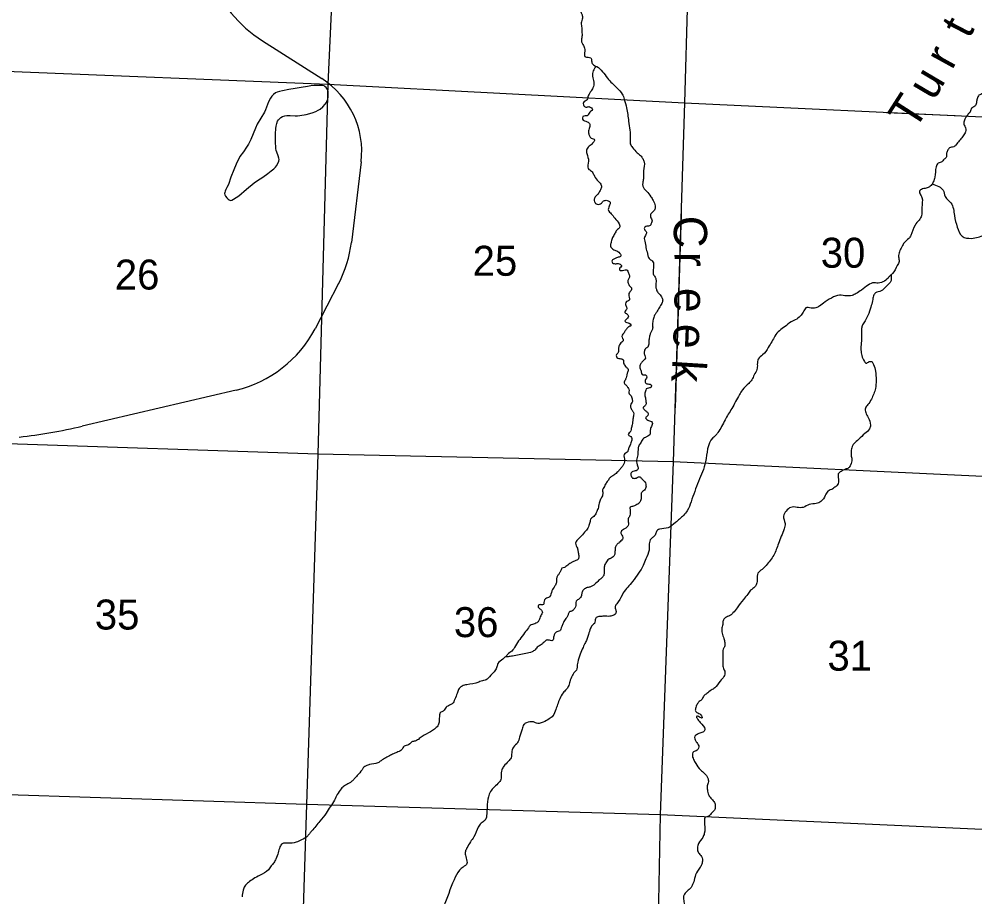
# Model space of a CAD drawing. Extents: x 1219626 to 1426462, y 456797 to 752399.
# Drawn here: x 1266561 to 1280912, y 533009 to 546194 of the extents above; entities that cross this region are included whole.
import ezdxf

# ---------------------------------------------------------------- set-up
doc = ezdxf.new("R2010")
doc.units = 0
for name, color, linetype in [('Lakes and Ponds', 7, 'Continuous'), ('Masks', 7, 'Continuous'), ('Narrow River Creek and Branch and Slough', 7, 'Continuous'), ('Narrow River Creek and Branch and Slough Text', 7, 'Continuous'), ('Section Lines', 7, 'Continuous'), ('Section Numbers', 7, 'Continuous'), ('Uninventoried Roads and Features', 7, 'Continuous')]:
    doc.layers.add(name, color=color, linetype=linetype)

msp = doc.modelspace()

# ---------------------------------------------------------------- linework, layer by layer
at = {"layer": 'Lakes and Ponds'}
msp.add_lwpolyline([(1269876, 544129), (1269818, 544016), (1269783, 543929), (1269742, 543820), (1269703, 543711), (1269682, 543667), (1269664, 543634), (1269653, 543609), (1269648, 543590), (1269646, 543576), (1269649, 543555), (1269658, 543534), (1269679, 543507), (1269698, 543489), (1269713, 543478), (1269724, 543473), (1269741, 543469), (1269757, 543473), (1269782, 543487), (1269821, 543513), (1269858, 543542), (1269975, 543639), (1270090, 543734), (1270140, 543771), (1270218, 543821), (1270296, 543873), (1270347, 543913), (1270384, 543945), (1270409, 543971), (1270426, 543991), (1270446, 544024), (1270461, 544060), (1270464, 544083), (1270462, 544103), (1270451, 544139), (1270429, 544194), (1270420, 544222), (1270415, 544250), (1270411, 544361), (1270411, 544472), (1270415, 544549), (1270421, 544588), (1270429, 544627), (1270442, 544660), (1270456, 544683), (1270469, 544698), (1270491, 544718), (1270518, 544732), (1270550, 544740), (1270579, 544744), (1270629, 544745), (1270704, 544742), (1270741, 544742), (1270778, 544745), (1270869, 544763), (1270960, 544787), (1271015, 544807), (1271053, 544826), (1271080, 544843), (1271120, 544874), (1271157, 544914), (1271172, 544936), (1271183, 544956), (1271196, 544993), (1271201, 545021), (1271203, 545062), (1271200, 545102), (1271192, 545136), (1271183, 545152), (1271170, 545168), (1271153, 545182), (1271139, 545190), (1271117, 545197), (1271095, 545199), (1270992, 545196), (1270940, 545191), (1270889, 545184), (1270797, 545168), (1270705, 545152), (1270609, 545135), (1270514, 545118), (1270470, 545108), (1270437, 545096), (1270413, 545085), (1270381, 545063), (1270354, 545035), (1270334, 545006), (1270308, 544954), (1270278, 544873), (1270262, 544833), (1270243, 544795), (1270188, 544705), (1270136, 544615), (1270109, 544558), (1270075, 544471), (1270039, 544385), (1270004, 544318), (1269975, 544269), (1269928, 544198), (1269876, 544129)], dxfattribs=at)
at = {"layer": 'Masks'}
for p, q in [((1279585, 544793), (1280614, 544744)), ((1276500, 543269), (1276409, 540356))]:
    msp.add_line(p, q, dxfattribs=at)
at = {"layer": 'Narrow River Creek and Branch and Slough'}
for points in [[(1273909, 549297), (1273931, 549227), (1273957, 549175), (1274000, 549110), (1274044, 549058), (1274087, 549019), (1274148, 548967), (1274191, 548928), (1274200, 548897), (1274213, 548867), (1274243, 548850), (1274308, 548841), (1274343, 548858), (1274399, 548867), (1274417, 548841), (1274460, 548785), (1274486, 548746), (1274504, 548693), (1274504, 548641), (1274512, 548602), (1274508, 548576), (1274495, 548546), (1274530, 548511), (1274569, 548476), (1274612, 548437), (1274612, 548359), (1274603, 548294), (1274586, 548251), (1274560, 548199), (1274525, 548155), (1274525, 548112), (1274556, 548077), (1274595, 548034), (1274647, 547964), (1274664, 547890), (1274694, 547804), (1274712, 547751), (1274729, 547717), (1274760, 547678), (1274799, 547647), (1274872, 547643), (1274920, 547656), (1274976, 547647), (1275024, 547617), (1275037, 547582), (1275050, 547539), (1275083, 547465), (1275127, 547399), (1275131, 547356), (1275114, 547291), (1275088, 547200), (1275079, 547156), (1275048, 547126), (1275022, 547091), (1274992, 547026), (1274979, 546935), (1274975, 546818), (1274979, 546735), (1274975, 546692), (1274949, 546653), (1274923, 546601), (1274918, 546544), (1274931, 546483), (1274966, 546397), (1274966, 546349), (1274996, 546301), (1275014, 546258), (1275018, 546210), (1275001, 546136), (1275009, 546062), (1275009, 546010), (1275014, 545967), (1275005, 545897), (1275005, 545854), (1275027, 545811), (1275048, 545759), (1275057, 545715), (1275048, 545667), (1275057, 545633), (1275105, 545620), (1275144, 545611), (1275157, 545568), (1275161, 545537), (1275200, 545498), (1275235, 545481), (1275396, 545307), (1275539, 545159), (1275617, 545068), (1275647, 544990), (1275682, 544859), (1275712, 544660)], [(1281992, 546706), (1281965, 546641), (1281938, 546593), (1281911, 546561), (1281874, 546539), (1281810, 546523), (1281777, 546486), (1281772, 546437), (1281820, 546395), (1281815, 546368), (1281777, 546341), (1281745, 546325), (1281713, 546293), (1281686, 546250), (1281681, 546212), (1281697, 546132), (1281702, 546084), (1281681, 546041), (1281659, 546019), (1281627, 546025), (1281595, 546003), (1281579, 545901), (1281542, 545853), (1281472, 545783), (1281424, 545767), (1281386, 545751), (1281381, 545660), (1281354, 545569), (1281316, 545520), (1281274, 545494), (1281257, 545461), (1281231, 545402), (1281209, 545365), (1281188, 545333), (1281123, 545295), (1281081, 545252), (1281059, 545220), (1281032, 545150), (1281027, 545102), (1281016, 545070), (1280984, 545059), (1280952, 545011), (1280936, 544957), (1280931, 544920), (1280898, 544877), (1280861, 544855), (1280839, 544802), (1280813, 544770), (1280780, 544721), (1280754, 544678), (1280748, 544614), (1280770, 544560), (1280764, 544485), (1280727, 544426), (1280625, 544303), (1280593, 544276), (1280529, 544260), (1280502, 544217), (1280486, 544168), (1280486, 544126), (1280448, 544088), (1280416, 544050), (1280362, 544029), (1280330, 543975), (1280309, 543820), (1280287, 543750), (1280255, 543697), (1280196, 543659), (1280127, 543643), (1280078, 543605), (1280089, 543568), (1280116, 543514), (1280116, 543364), (1280110, 543241), (1280073, 543176), (1280014, 543101), (1279950, 542946), (1279918, 542897), (1279853, 542839), (1279816, 542774), (1279778, 542699), (1279767, 542624), (1279773, 542554), (1279746, 542495), (1279674, 542371), (1279636, 542337), (1279608, 542304), (1279438, 542229), (1279400, 542233), (1279310, 542200), (1279211, 542124)], [(1275222, 545489), (1275182, 545415), (1275169, 545337), (1275189, 545247), (1275176, 545163), (1275143, 545105), (1275118, 545066), (1275098, 545014), (1275085, 544982), (1275034, 544943), (1275034, 544904), (1275072, 544872), (1275118, 544879), (1275169, 544833), (1275130, 544795), (1275092, 544743), (1275027, 544730), (1275021, 544691), (1275092, 544652), (1275130, 544614), (1275118, 544549), (1275111, 544484), (1275124, 544439), (1275150, 544407), (1275201, 544381), (1275182, 544342), (1275137, 544297), (1275085, 544239), (1275085, 544174), (1275111, 544058), (1275105, 543948), (1275156, 543909), (1275189, 543858), (1275240, 543774), (1275285, 543728), (1275305, 543670), (1275285, 543619), (1275253, 543567), (1275221, 543535), (1275195, 543489), (1275201, 543451), (1275240, 543412), (1275305, 543431), (1275337, 543464), (1275389, 543470), (1275434, 543444), (1275421, 543386), (1275408, 543321), (1275453, 543270), (1275505, 543205), (1275570, 543121), (1275576, 543063), (1275537, 543024), (1275505, 542972), (1275473, 542914), (1275453, 542850), (1275440, 542798), (1275466, 542746), (1275518, 542720), (1275582, 542675), (1275595, 542636), (1275557, 542617), (1275511, 542598), (1275473, 542578), (1275460, 542559), (1275473, 542533), (1275524, 542520), (1275570, 542520), (1275608, 542481), (1275582, 542456), (1275576, 542430), (1275641, 542423), (1275679, 542430), (1275712, 542378), (1275725, 542333), (1275718, 542300), (1275699, 542255), (1275705, 542229), (1275731, 542184), (1275757, 542145), (1275750, 542120), (1275718, 542074), (1275718, 542036), (1275718, 541965), (1275679, 541952), (1275666, 541919), (1275679, 541868), (1275686, 541842), (1275654, 541797), (1275666, 541777), (1275684, 541770)], [(1280272, 543718), (1280370, 543678), (1280434, 543625), (1280466, 543529), (1280508, 543476), (1280551, 543433), (1280604, 543242), (1280647, 543071), (1280721, 542933), (1280859, 542901), (1281051, 542954), (1281274, 543093), (1281402, 543167), (1281541, 543220), (1281700, 543220), (1281828, 543220), (1281934, 543306), (1282073, 543327), (1282211, 543327), (1282349, 543263), (1282456, 543284), (1282637, 543306), (1282860, 543316), (1283063, 543370), (1283222, 543370), (1283403, 543359), (1283541, 543348), (1283744, 543391), (1284020, 543487), (1284212, 543529), (1284404, 543561), (1284553, 543615), (1284702, 543668), (1284904, 543710), (1285127, 543785), (1285393, 543849), (1285606, 543870), (1285766, 543902), (1285926, 543902), (1286053, 543966), (1286234, 544009), (1286458, 544051), (1286713, 544051), (1286820, 544072), (1286915, 544009), (1286979, 543987), (1287064, 544062), (1287181, 544136), (1287309, 544200), (1287543, 544222), (1287809, 544243), (1287937, 544243), (1288033, 544307), (1288118, 544371), (1288256, 544445), (1288310, 544498), (1288437, 544573), (1288533, 544647), (1288629, 544733), (1288714, 544829), (1288767, 544914), (1288821, 545020), (1288852, 545073), (1288916, 545180)], [(1275712, 544660), (1275730, 544525), (1275738, 544416), (1275738, 544321), (1275769, 544265), (1275842, 544186), (1275890, 544143), (1275925, 544100), (1275947, 544048), (1275938, 543917), (1275934, 543796), (1275925, 543735), (1275925, 543687), (1275981, 543609), (1276046, 543527), (1276081, 543470), (1276111, 543388), (1276107, 543340), (1276072, 543292), (1276046, 543269), (1276042, 543222), (1276064, 543165), (1276055, 543135), (1276038, 543096), (1276012, 543083), (1275986, 543083), (1275955, 543070), (1275955, 543026), (1275981, 542996), (1275973, 542961), (1275947, 542900), (1275955, 542857), (1275973, 542761), (1275994, 542675), (1276007, 542627), (1276042, 542579), (1276068, 542562), (1276085, 542531), (1276085, 542453), (1276081, 542410), (1276081, 542366), (1276111, 542319), (1276124, 542271), (1276120, 542180), (1276129, 542136), (1276151, 542088), (1276185, 542054), (1276207, 542023), (1276224, 541976), (1276211, 541924), (1276172, 541858), (1276129, 541789), (1276103, 541746), (1276081, 541680), (1276072, 541611), (1276072, 541550), (1276055, 541507), (1276038, 541468), (1276025, 541420), (1276016, 541355), (1276012, 541298), (1275999, 541268), (1275968, 541246), (1275947, 541194), (1275955, 541142), (1275964, 541103), (1275942, 541073), (1275912, 541042), (1275886, 540999), (1275886, 540942), (1275903, 540895), (1275916, 540856), (1275938, 540851), (1275968, 540851), (1275986, 540817), (1275968, 540782), (1275968, 540729), (1276016, 540712), (1276051, 540703), (1276051, 540669), (1276012, 540651), (1275977, 540638), (1275964, 540603), (1275955, 540551), (1275968, 540491), (1275973, 540443), (1275968, 540395), (1275955, 540382), (1275929, 540360), (1275951, 540326), (1275986, 540295)], [(1279654, 542352), (1279655, 542312), (1279655, 542270), (1279631, 542227), (1279570, 542166), (1279504, 542113), (1279419, 542080), (1279390, 542038), (1279376, 541962), (1279348, 541867), (1279305, 541744), (1279262, 541664), (1279225, 541602), (1279210, 541545), (1279210, 541437), (1279201, 541224), (1279253, 541053), (1279281, 541025), (1279324, 541049), (1279367, 541044), (1279390, 541006), (1279419, 540907), (1279428, 540769), (1279419, 540646), (1279357, 540484), (1279305, 540403), (1279267, 540351), (1279272, 540285), (1279310, 540209), (1279343, 540096), (1279329, 540039), (1279258, 539968), (1279168, 539883), (1279092, 539812), (1279069, 539774), (1279054, 539698), (1279054, 539641), (1279064, 539584), (1279045, 539495), (1279012, 539452), (1278969, 539433), (1278903, 539400), (1278860, 539362), (1278860, 539315), (1278841, 539187), (1278808, 539163), (1278780, 539140), (1278704, 539102), (1278666, 539040), (1278600, 538950), (1278529, 538917), (1278425, 538903), (1278335, 538860), (1278241, 538860), (1278146, 538860), (1278080, 538804), (1278037, 538728), (1278061, 538619), (1278047, 538538), (1277962, 538316), (1277891, 538141), (1277777, 537989), (1277716, 537928), (1277654, 537871), (1277643, 537780)], [(1279211, 542124), (1279130, 542072), (1279069, 542044), (1278960, 542039), (1278851, 542044), (1278790, 542020), (1278662, 541945), (1278577, 541883), (1278525, 541859), (1278430, 541859), (1278387, 541864), (1278345, 541812), (1278302, 541746), (1278236, 541689), (1278151, 541646), (1278061, 541575), (1277976, 541514), (1277910, 541433), (1277862, 541348), (1277810, 541263), (1277725, 541149), (1277659, 541088), (1277645, 541007), (1277640, 540932), (1277598, 540851), (1277564, 540776), (1277517, 540723), (1277422, 540624), (1277375, 540553), (1277261, 540344), (1277209, 540259), (1277161, 540173), (1277109, 540074), (1277053, 539984), (1277029, 539951), (1276977, 539904), (1276868, 539544), (1276764, 539251), (1276650, 538943), (1276594, 538810), (1276537, 538739), (1276414, 538631), (1276305, 538555), (1276177, 538531), (1276144, 538517), (1276121, 538470), (1276092, 538422), (1276050, 538389), (1276021, 538313), (1276021, 538219), (1275969, 538086), (1275931, 537987), (1275861, 537873), (1275771, 537745), (1275633, 537575), (1275558, 537442), (1275515, 537381), (1275515, 537333), (1275525, 537286), (1275492, 537243), (1275430, 537224), (1275340, 537224), (1275283, 537220), (1275227, 537206), (1275208, 537158), (1275198, 537116), (1275175, 537097), (1275142, 537045), (1275108, 536950), (1275089, 536888), (1275066, 536832), (1275028, 536756), (1274985, 536657), (1274948, 536533), (1274938, 536458), (1274929, 536415), (1274891, 536373), (1274867, 536330), (1274829, 536240), (1274806, 536169), (1274777, 536126), (1274730, 536074), (1274678, 535984), (1274645, 535899), (1274621, 535824), (1274574, 535729), (1274522, 535682), (1274432, 535634), (1274370, 535615), (1274328, 535620), (1274285, 535639)], [(1275684, 541770), (1275709, 541731), (1275697, 541701), (1275675, 541684), (1275658, 541662), (1275671, 541641), (1275705, 541632), (1275735, 541619), (1275748, 541589), (1275731, 541580), (1275688, 541546), (1275658, 541507), (1275628, 541460), (1275610, 541429), (1275623, 541399), (1275632, 541373), (1275598, 541330), (1275576, 541300), (1275563, 541257), (1275559, 541201), (1275550, 541175), (1275529, 541154), (1275529, 541124), (1275550, 541102), (1275610, 541089), (1275636, 541072), (1275636, 541042), (1275658, 540990), (1275679, 540964), (1275705, 540934), (1275697, 540887), (1275684, 540844), (1275675, 540805), (1275658, 540766), (1275645, 540740), (1275649, 540719), (1275679, 540693), (1275701, 540658), (1275718, 540633), (1275718, 540594), (1275722, 540564), (1275753, 540533), (1275761, 540503), (1275770, 540452), (1275757, 540426), (1275740, 540391), (1275740, 540366), (1275765, 540318), (1275787, 540284), (1275787, 540245), (1275778, 540185), (1275765, 540098), (1275753, 540047), (1275744, 540012), (1275735, 539991), (1275709, 539965), (1275709, 539948), (1275744, 539922), (1275761, 539892), (1275753, 539844), (1275727, 539780), (1275709, 539732), (1275692, 539689), (1275658, 539668), (1275641, 539633), (1275649, 539590), (1275649, 539542), (1275636, 539503), (1275610, 539465), (1275585, 539434), (1275550, 539396), (1275524, 539370), (1275477, 539335), (1275438, 539310), (1275408, 539271), (1275374, 539223), (1275339, 539159), (1275322, 539124), (1275326, 539086), (1275318, 539034), (1275292, 538982), (1275270, 538922), (1275262, 538879), (1275253, 538844), (1275227, 538780), (1275189, 538724), (1275141, 538681), (1275133, 538646), (1275115, 538586), (1275102, 538547), (1275051, 538487)], [(1275986, 540295), (1276003, 540282), (1276007, 540260), (1275986, 540226), (1275968, 540208), (1275986, 540178), (1276042, 540156), (1276068, 540135), (1276068, 540104), (1276042, 540043), (1276038, 539991), (1276029, 539952), (1275999, 539931), (1275964, 539909), (1275938, 539896), (1275899, 539839), (1275864, 539783), (1275855, 539731), (1275851, 539674), (1275847, 539627), (1275834, 539588), (1275842, 539501), (1275851, 539470), (1275855, 539444), (1275842, 539418), (1275777, 539401), (1275747, 539371), (1275747, 539344), (1275773, 539301), (1275825, 539301), (1275860, 539318), (1275882, 539318), (1275912, 539288), (1275964, 539227), (1275973, 539184), (1275973, 539158), (1275938, 539110), (1275903, 539071), (1275903, 539019), (1275890, 538958), (1275864, 538919), (1275834, 538902), (1275786, 538876), (1275738, 538863), (1275734, 538824), (1275738, 538776), (1275730, 538737), (1275708, 538689), (1275704, 538659), (1275712, 538628), (1275708, 538589), (1275669, 538550), (1275634, 538528), (1275595, 538481), (1275613, 538442), (1275626, 538407), (1275621, 538381), (1275595, 538355), (1275573, 538332), (1275534, 538297), (1275513, 538254), (1275508, 538197), (1275504, 538158), (1275482, 538119), (1275452, 538097), (1275413, 538080), (1275370, 538028), (1275348, 537976), (1275344, 537915), (1275344, 537863), (1275326, 537815), (1275287, 537780), (1275239, 537737), (1275170, 537681), (1275131, 537663), (1275079, 537650), (1275027, 537611), (1275009, 537563), (1275005, 537537), (1274970, 537485), (1274927, 537451), (1274914, 537364), (1274888, 537325), (1274862, 537299), (1274832, 537294), (1274810, 537268), (1274797, 537225), (1274771, 537190), (1274749, 537160), (1274719, 537095), (1274701, 537051)], [(1275051, 538487), (1274986, 538414), (1274943, 538371), (1274917, 538323), (1274926, 538284), (1274947, 538237), (1274956, 538181), (1274965, 538121), (1274952, 538078), (1274909, 538056), (1274866, 538039), (1274831, 538017), (1274771, 537970), (1274749, 537957), (1274711, 537948), (1274698, 537923), (1274681, 537884), (1274659, 537849), (1274633, 537811), (1274629, 537763), (1274629, 537733), (1274607, 537681), (1274560, 537604), (1274526, 537518), (1274508, 537505), (1274478, 537496), (1274452, 537470), (1274439, 537431), (1274439, 537410), (1274422, 537397), (1274371, 537397), (1274353, 537376), (1274366, 537350), (1274396, 537324), (1274418, 537287), (1274392, 537231), (1274366, 537162), (1274336, 537127), (1274267, 537101), (1274233, 537084), (1274207, 537050), (1274151, 536976), (1274078, 536877), (1274013, 536778), (1273957, 536701), (1273897, 536653), (1273868, 536613)], [(1277643, 537780), (1277634, 537709), (1277610, 537666), (1277544, 537614), (1277501, 537558), (1277435, 537477), (1277341, 537349), (1277279, 537274), (1277241, 537240), (1277180, 537212), (1277142, 537179), (1277128, 537132), (1277128, 537117), (1277113, 537051), (1277118, 536971), (1277142, 536890), (1277156, 536829), (1277151, 536767), (1277132, 536729), (1277128, 536644), (1277128, 536493), (1277142, 536426), (1277156, 536398), (1277156, 536355), (1277142, 536318), (1277085, 536251), (1277005, 536147), (1276953, 536114), (1276886, 536062), (1276844, 536029), (1276815, 535981), (1276773, 535944)], [(1274701, 537051), (1274688, 537016), (1274636, 536990), (1274615, 536977), (1274597, 536947), (1274584, 536899), (1274580, 536869), (1274558, 536856), (1274524, 536864), (1274476, 536864), (1274432, 536825), (1274402, 536799), (1274354, 536769), (1274307, 536721), (1274263, 536691), (1274168, 536665), (1274068, 536643), (1273968, 536626), (1273903, 536617), (1273864, 536613), (1273825, 536582), (1273751, 536513), (1273736, 536465), (1273723, 536434), (1273684, 536378), (1273602, 536295), (1273575, 536269), (1273536, 536261), (1273463, 536235), (1273285, 536196), (1273211, 536174), (1273159, 536126), (1273137, 536065), (1273103, 535979), (1273064, 535909), (1273024, 535887), (1272972, 535857), (1272951, 535827), (1272929, 535801), (1272886, 535779), (1272873, 535731), (1272868, 535662), (1272860, 535605), (1272825, 535553), (1272582, 535397), (1272530, 535358), (1272482, 535345), (1272456, 535336), (1272426, 535306), (1272391, 535288), (1272330, 535262), (1272313, 535228), (1272265, 535193), (1272200, 535167), (1272139, 535136), (1271996, 535054), (1271948, 535023), (1271823, 534997), (1271771, 534976), (1271736, 534958), (1271710, 534919), (1271636, 534832), (1271593, 534780), (1271558, 534746), (1271515, 534715), (1271445, 534676), (1271397, 534633), (1271337, 534546), (1271298, 534463), (1271233, 534364), (1271172, 534268), (1271076, 534147), (1270955, 533999), (1270928, 533968), (1270894, 533925), (1270803, 533864), (1270720, 533829), (1270599, 533816), (1270512, 533808), (1270477, 533760), (1270451, 533673), (1270416, 533578), (1270386, 533521), (1270347, 533473), (1270304, 533417), (1270178, 533334), (1270078, 533278), (1270004, 533226), (1269948, 533169), (1269926, 533109), (1269909, 533009)], [(1276773, 535944), (1276740, 535901), (1276716, 535839), (1276721, 535792), (1276754, 535773), (1276806, 535730), (1276815, 535697), (1276778, 535711), (1276749, 535725), (1276730, 535716), (1276740, 535692), (1276787, 535626), (1276858, 535527), (1276839, 535489), (1276782, 535470), (1276730, 535441), (1276707, 535422), (1276707, 535385), (1276716, 535356), (1276759, 535295), (1276768, 535261), (1276754, 535224), (1276726, 535205), (1276678, 535176), (1276674, 535138), (1276674, 535110), (1276688, 535072), (1276721, 535015), (1276792, 534916), (1276853, 534864), (1276901, 534793), (1276910, 534741), (1276891, 534675), (1276896, 534618), (1276915, 534537), (1276962, 534476), (1277000, 534428), (1277014, 534372), (1277000, 534310), (1276962, 534272), (1276920, 534225), (1276858, 534197), (1276853, 534163), (1276853, 534097), (1276849, 533960), (1276825, 533903), (1276763, 533813), (1276745, 533742), (1276749, 533700), (1276782, 533648), (1276820, 533577), (1276815, 533515), (1276787, 533453), (1276745, 533397), (1276702, 533283), (1276674, 533193), (1276650, 533151), (1276542, 533032), (1276537, 532975), (1276552, 532895), (1276570, 532805), (1276556, 532734), (1276528, 532667), (1276481, 532606), (1276447, 532554), (1276419, 532454), (1276386, 532374), (1276310, 532303), (1276277, 532251), (1276258, 532194), (1276216, 532123), (1276140, 532076), (1276097, 532033), (1276055, 531962), (1276012, 531905), (1275842, 531778), (1275653, 531669), (1275516, 531607), (1275364, 531593), (1275208, 531598), (1275123, 531574), (1274995, 531522), (1274858, 531456), (1274763, 531385), (1274645, 531304), (1274314, 531077), (1274139, 530959), (1273978, 530874), (1273794, 530822), (1273448, 530703), (1273202, 530561)], [(1274285, 535639), (1274177, 535625), (1274139, 535596), (1274115, 535530), (1274072, 535407), (1274046, 535326), (1273985, 535260), (1273957, 535175), (1273947, 535099), (1273909, 535047), (1273838, 534971), (1273810, 534919), (1273800, 534825), (1273800, 534791), (1273767, 534730), (1273696, 534659), (1273640, 534593), (1273607, 534512), (1273588, 534361), (1273583, 534257), (1273559, 534162), (1273498, 534115), (1273455, 534058), (1273389, 533911), (1273337, 533835), (1273285, 533745), (1273261, 533689), (1273261, 533637), (1273285, 533547), (1273285, 533509), (1273228, 533457), (1273171, 533409), (1273091, 533267), (1272930, 532860), (1272796, 532595), (1272739, 532505), (1272664, 532405), (1272635, 532344), (1272545, 532259), (1272342, 532102), (1272172, 531975), (1272091, 531894), (1272072, 531842), (1271926, 531700), (1271651, 531435), (1271467, 531269), (1271306, 531165), (1271008, 531018), (1270696, 530891), (1270563, 530820), (1270403, 530725), (1270105, 530545), (1269679, 530313), (1269580, 530285), (1269494, 530247), (1269365, 530195), (1269351, 530171), (1269323, 530138), (1269214, 530095), (1269157, 530095), (1269100, 530100), (1269067, 530100), (1268958, 530067), (1268835, 530034), (1268731, 530001), (1268660, 529968), (1268585, 529911), (1268533, 529878), (1268410, 529816), (1268339, 529783), (1268268, 529750), (1268202, 529702), (1268107, 529650), (1267956, 529575), (1267818, 529527), (1267658, 529471), (1267511, 529423), (1267246, 529324), (1267161, 529248), (1267104, 529191), (1266986, 529158), (1266920, 529097), (1266849, 529045), (1266806, 529007), (1266754, 528940), (1266759, 528893), (1266735, 528841), (1266702, 528780), (1266660, 528713), (1266626, 528642), (1266603, 528600)]]:
    msp.add_spline(points, degree=3, dxfattribs=at)
at = {"layer": 'Section Lines'}
for p, q in [((1271434, 550515), (1271197, 545219)), ((1276702, 550226), (1276552, 544938)), ((1265930, 545430), (1271197, 545219)), ((1271197, 545219), (1271044, 539660)), ((1271197, 545219), (1276552, 544938)), ((1276552, 544938), (1276383, 539544)), ((1276552, 544938), (1281788, 544688)), ((1271044, 539660), (1265724, 539837)), ((1271044, 539660), (1270876, 534399)), ((1276383, 539544), (1271044, 539660)), ((1276383, 539544), (1276187, 534239)), ((1281504, 539299), (1276383, 539544)), ((1270876, 534399), (1265556, 534569)), ((1270876, 534399), (1270710, 529193)), ((1276187, 534239), (1270876, 534399)), ((1276187, 534239), (1276086, 528970)), ((1281497, 533999), (1276187, 534239))]:
    msp.add_line(p, q, dxfattribs=at)
at = {"layer": 'Uninventoried Roads and Features'}
for p, q in [((1270217, 545868), (1271104, 545302)), ((1271696, 544051), (1271550, 542840)), ((1271359, 542224), (1271004, 541542)), ((1269820, 540622), (1267509, 540079))]:
    msp.add_line(p, q, dxfattribs=at)
for centre, radius, start, end in [((1271346, 547639), 2100, 169.3852, 237.4698), ((1270405, 544206), 1300, 353.1205, 57.4698), ((1269763, 543056), 1800, 332.465, 353.1205), ((1269408, 542375), 1800, 283.2221, 332.465), ((1265679, 547867), 8000, 276.3277, 283.2221)]:
    msp.add_arc(centre, radius, start, end, dxfattribs=at)

# ---------------------------------------------------------------- texts
at = {"layer": 'Narrow River Creek and Branch and Slough Text'}
for s, rotation, p in [('t', 62.5092, (1280826, 545885)), ('r', 61.0666, (1280567, 545417)), ('u', 59.3704, (1280294, 544956)), ('T', 57.3785, (1280005, 544505)), ('C', 271.9937, (1276382, 543231)), ('r', 270.3337, (1276401, 542696)), ('e', 268.9432, (1276404, 542161)), ('e', 267.6425, (1276394, 541625)), ('k', 266.4245, (1276372, 541090))]:
    msp.add_text(s, height=500, rotation=rotation, dxfattribs=at).set_placement(p)
at = {"layer": 'Section Numbers'}
for s, p in [('30', (1278597, 542460)), ('25', (1273371, 542339)), ('26', (1267998, 542132)), ('35', (1267698, 537025)), ('36', (1273089, 536911)), ('31', (1278698, 536407))]:
    msp.add_text(s, height=450, rotation=0.0004, dxfattribs=at).set_placement(p)

doc.saveas('drawing.dxf')
